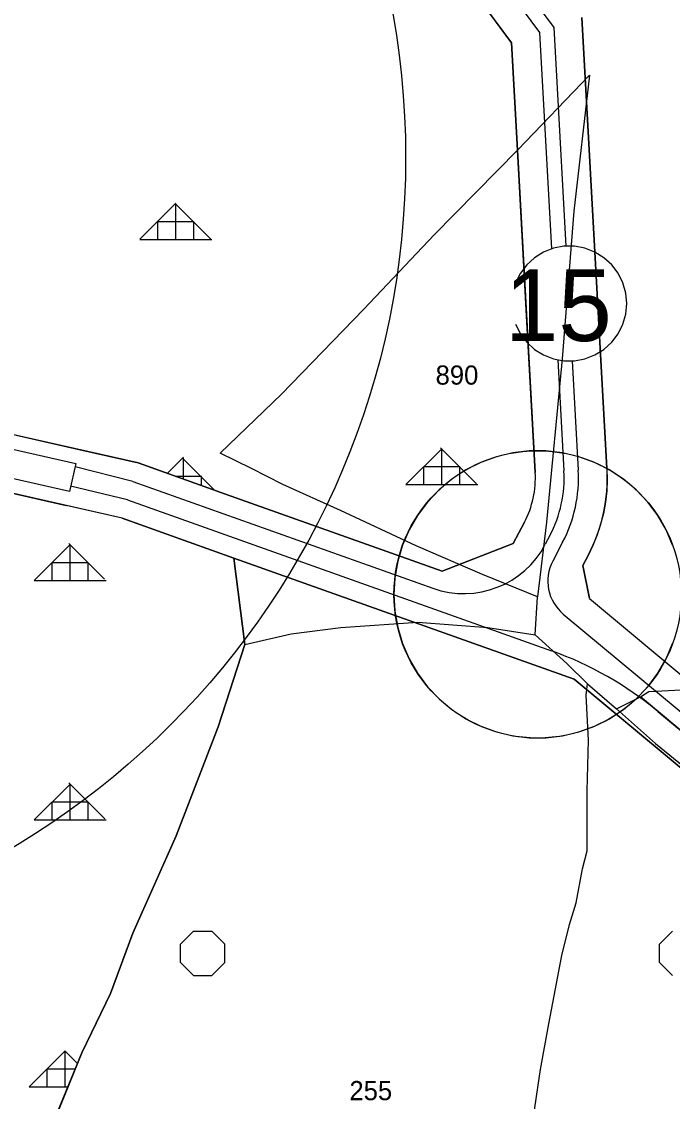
# Model space of a CAD drawing. Extents: x 410727 to 412947, y 4463506 to 4466382.
# Drawn here: x 411560.6 to 411696.5, y 4465556.3 to 4465781.8 of the extents above; entities that cross this region are included whole.
import ezdxf

# ---------------------------------------------------------------- set-up
doc = ezdxf.new("R2010")
doc.units = 0
for name, color, linetype in [('ADAKENARI', 7, 'Continuous'), ('KALDIRIM', 7, 'Continuous'), ('KAVSAK_BEYAZ', 7, 'Continuous'), ('KD_DAIRE', 7, 'Continuous'), ('KD_YGEN', 7, 'Continuous'), ('KDS_PARSEL_NO', 7, 'Continuous'), ('KDS_PL', 7, 'Continuous'), ('LJ_ÇERÇEVE', 7, 'Continuous'), ('PL_AYA_ORMAN', 7, 'Continuous'), ('PL_KA_TARIM_DIGER', 7, 'Continuous'), ('TR_AGACALANI', 7, 'Continuous'), ('TR_ORMAN', 7, 'Continuous'), ('TR_TARIMALANI', 7, 'Continuous')]:
    doc.layers.add(name, color=color, linetype=linetype)

msp = doc.modelspace()

# ---------------------------------------------------------------- linework, layer by layer
at = {"layer": 'ADAKENARI'}
for p, q in [((411615.28, 4465841.88), (411662.84, 4465777.4)), ((411682.8, 4465688.51), (411677.57, 4465782.7)), ((411662.84, 4465777.4), (411664.09, 4465754.96)), ((411664.19, 4465755.05), (411664.09, 4465754.96)), ((411664.09, 4465754.96), (411667.83, 4465687.68)), ((411584.92, 4465689.65), (411487.47, 4465711.77)), ((411451.42, 4465707.64), (411569.91, 4465680.75)), ((411581.57, 4465678.11), (411469.07, 4465703.64)), ((411581.57, 4465678.11), (411469.07, 4465703.64)), ((411572.56, 4465692.45), (411537.97, 4465700.31)), ((411603.17, 4465683.15), (411584.92, 4465689.65)), ((411648.41, 4465667.03), (411603.17, 4465683.15)), ((411581.57, 4465678.11), (411604.87, 4465669.8)), ((411581.57, 4465678.11), (411604.87, 4465669.8)), ((411665.57, 4465677.27), (411663.23, 4465672.82)), ((411663.23, 4465672.82), (411648.41, 4465667.03)), ((411677.76, 4465668.23), (411678.85, 4465670.3)), ((411604.87, 4465669.8), (411675.96, 4465644.48)), ((411604.87, 4465669.8), (411607.17, 4465651.76)), ((411679.13, 4465661.35), (411677.76, 4465668.23)), ((411679.13, 4465661.35), (411700.95, 4465643.19)), ((411607.17, 4465651.76), (411601.65, 4465634.53)), ((411675.96, 4465644.48), (411739.57, 4465591.54)), ((411601.65, 4465634.53), (411592.83, 4465611.76)), ((411592.83, 4465611.76), (411583.79, 4465591.43)), ((411583.79, 4465591.43), (411579.16, 4465578.83)), ((411579.16, 4465578.83), (411573.2, 4465566.46)), ((411573.2, 4465566.46), (411563.28, 4465542.37))]:
    msp.add_line(p, q, dxfattribs=at)
for radius in [35, 35, 20, 20]:
    msp.add_arc((411647.86, 4465686.57), radius, 332.3005, 3.1798, dxfattribs=at)
at = {"layer": 'KALDIRIM'}
for p, q in [((411622.53, 4465847.22), (411671.68, 4465780.58)), ((411620.11, 4465845.44), (411668.73, 4465779.52)), ((411668.73, 4465779.52), (411671.24, 4465734.36)), ((411671.68, 4465780.58), (411674.22, 4465734.92)), ((411672.53, 4465711.18), (411673.82, 4465688.01)), ((411675.55, 4465710.95), (411676.81, 4465688.17)), ((411583.8, 4465685.8), (411571.74, 4465688.85)), ((411582.69, 4465681.95), (411570.82, 4465684.83)), ((411583.8, 4465685.8), (411646.44, 4465663.49)), ((411582.69, 4465681.95), (411671.24, 4465650.4)), ((411670.88, 4465674.48), (411669.92, 4465672.66)), ((411673.53, 4465673.09), (411671.47, 4465669.16)), ((411673.68, 4465658.08), (411745.02, 4465598.7)), ((411693.39, 4465637.78), (411743.2, 4465596.32))]:
    msp.add_line(p, q, dxfattribs=at)
msp.add_lwpolyline([(411453.41, 4465716.42), (411571.9, 4465689.53), (411570.57, 4465683.68), (411452.08, 4465710.57)], dxfattribs=at)
for centre, radius, start, end in [((411647.86, 4465686.57), 26, 332.3005, 3.1798), ((411647.86, 4465686.57), 26, 332.3005, 3.1798), ((411647.86, 4465686.57), 29, 332.3005, 3.1798), ((411647.86, 4465686.57), 29, 332.3005, 3.1798), ((411652.9, 4465681.6), 19.23, 250.3903, 332.3005), ((411652.9, 4465681.6), 19.23, 250.3903, 332.3005), ((411679.43, 4465664.99), 8.98, 152.3005, 230.2295), ((411679.43, 4465664.99), 8.98, 152.3005, 230.2295), ((411646.8, 4465581.8), 72.83, 50.2294, 70.3903), ((411646.8, 4465581.8), 72.83, 50.2294, 70.3903)]:
    msp.add_arc(centre, radius, start, end, dxfattribs=at)
at = {"layer": 'KAVSAK_BEYAZ'}
msp.add_lwpolyline([(411696.51, 4465672.47), (411695.13, 4465675.67), (411693.38, 4465678.69), (411691.3, 4465681.49), (411688.9, 4465684.03), (411686.23, 4465686.27), (411683.32, 4465688.19), (411680.2, 4465689.75), (411676.92, 4465690.95), (411673.53, 4465691.75), (411670.06, 4465692.16), (411666.57, 4465692.16), (411663.11, 4465691.75), (411659.71, 4465690.95), (411656.43, 4465689.75), (411653.32, 4465688.19), (411650.4, 4465686.27), (411647.73, 4465684.03), (411645.34, 4465681.49), (411643.25, 4465678.69), (411641.51, 4465675.67), (411640.13, 4465672.47), (411639.13, 4465669.13), (411638.52, 4465665.69), (411638.32, 4465662.21), (411638.52, 4465658.73), (411639.13, 4465655.29), (411640.13, 4465651.95), (411641.51, 4465648.74), (411643.25, 4465645.72), (411645.34, 4465642.92), (411647.73, 4465640.39), (411650.4, 4465638.14), (411653.32, 4465636.23), (411656.43, 4465634.66), (411659.71, 4465633.47), (411663.11, 4465632.66), (411666.57, 4465632.26), (411670.06, 4465632.26), (411673.53, 4465632.66), (411676.92, 4465633.47), (411680.2, 4465634.66), (411683.32, 4465636.23), (411686.23, 4465638.14), (411688.9, 4465640.39), (411691.3, 4465642.92), (411693.38, 4465645.72), (411695.13, 4465648.74), (411696.51, 4465651.95)], dxfattribs=at)
at = {"layer": 'KD_DAIRE'}
for p, q in [((411669.56, 4465733.68), (411667.68, 4465732.51)), ((411671.63, 4465734.48), (411669.56, 4465733.68)), ((411673.8, 4465734.89), (411671.63, 4465734.48)), ((411676.02, 4465734.89), (411673.8, 4465734.89)), ((411678.19, 4465734.48), (411676.02, 4465734.89)), ((411680.26, 4465733.68), (411678.19, 4465734.48)), ((411682.14, 4465732.51), (411680.26, 4465733.68)), ((411667.68, 4465732.51), (411666.04, 4465731.02)), ((411683.78, 4465731.02), (411682.14, 4465732.51)), ((411664.71, 4465729.26), (411663.72, 4465727.27)), ((411666.04, 4465731.02), (411664.71, 4465729.26)), ((411685.11, 4465729.26), (411683.78, 4465731.02)), ((411686.1, 4465727.27), (411685.11, 4465729.26)), ((411686.71, 4465725.14), (411686.1, 4465727.27)), ((411686.91, 4465722.94), (411686.71, 4465725.14)), ((411686.71, 4465720.73), (411686.91, 4465722.94)), ((411686.91, 4465722.94), (411686.91, 4465722.94)), ((411686.1, 4465718.6), (411686.71, 4465720.73)), ((411663.72, 4465718.6), (411664.71, 4465716.62)), ((411685.11, 4465716.62), (411686.1, 4465718.6)), ((411664.71, 4465716.62), (411666.04, 4465714.85)), ((411683.78, 4465714.85), (411685.11, 4465716.62)), ((411666.04, 4465714.85), (411667.68, 4465713.36)), ((411667.68, 4465713.36), (411669.56, 4465712.2)), ((411680.26, 4465712.2), (411682.14, 4465713.36)), ((411682.14, 4465713.36), (411683.78, 4465714.85)), ((411669.56, 4465712.2), (411671.63, 4465711.4)), ((411671.63, 4465711.4), (411673.8, 4465710.99)), ((411673.8, 4465710.99), (411676.02, 4465710.99)), ((411676.02, 4465710.99), (411678.19, 4465711.4)), ((411678.19, 4465711.4), (411680.26, 4465712.2))]:
    msp.add_line(p, q, dxfattribs=at)
msp.add_circle((411668.32, 4465662.21), 30, dxfattribs=at)
at = {"layer": 'KDS_PL'}
for p, q in [((411664.19, 4465755.05), (411679.17, 4465770.61)), ((411679.17, 4465770.61), (411675.9, 4465742.23)), ((411646.75, 4465737.31), (411664.19, 4465755.05)), ((411675.9, 4465742.23), (411673.45, 4465711.38)), ((411632.04, 4465721.76), (411646.75, 4465737.31)), ((411614.88, 4465704.02), (411632.04, 4465721.76)), ((411673.45, 4465711.38), (411670.18, 4465677.27)), ((411602.08, 4465691.73), (411614.88, 4465704.02)), ((411608.62, 4465688.46), (411602.08, 4465691.73)), ((411615.16, 4465685.18), (411608.62, 4465688.46)), ((411627.14, 4465679.72), (411615.16, 4465685.18)), ((411642.94, 4465672.36), (411627.14, 4465679.72)), ((411670.18, 4465677.27), (411668.27, 4465661.71)), ((411656.83, 4465666.35), (411642.94, 4465672.36)), ((411668.27, 4465661.71), (411656.83, 4465666.35)), ((411667.82, 4465653.75), (411668.27, 4465661.71)), ((411616.87, 4465653.97), (411627.24, 4465655.3)), ((411627.24, 4465655.3), (411643.34, 4465656.4)), ((411643.34, 4465656.4), (411657.9, 4465655.3)), ((411657.9, 4465655.3), (411667.82, 4465653.75)), ((411607.17, 4465651.76), (411616.87, 4465653.97)), ((411667.82, 4465653.75), (411674.44, 4465647.79)), ((411601.65, 4465634.53), (411607.17, 4465651.76)), ((411674.44, 4465647.79), (411678.73, 4465643.55)), ((411678.42, 4465641.18), (411678.73, 4465643.55)), ((411678.73, 4465643.55), (411684.81, 4465638.29)), ((411678.94, 4465631.79), (411678.42, 4465641.18)), ((411689.77, 4465640.8), (411691.55, 4465641.9)), ((411691.55, 4465641.9), (411698.35, 4465642.24)), ((411684.81, 4465638.29), (411689.77, 4465640.8)), ((411708.29, 4465625.33), (411689.77, 4465640.8)), ((411684.81, 4465638.29), (411692.94, 4465631.07)), ((411592.83, 4465611.76), (411601.65, 4465634.53)), ((411678.63, 4465621.17), (411678.94, 4465631.79)), ((411692.94, 4465631.07), (411705.91, 4465620.45)), ((411678.69, 4465608.62), (411678.63, 4465621.17)), ((411583.79, 4465591.43), (411592.83, 4465611.76)), ((411677.71, 4465604.91), (411678.69, 4465608.62)), ((411676.4, 4465597.82), (411677.71, 4465604.91)), ((411674.99, 4465593.24), (411676.4, 4465597.82)), ((411579.16, 4465578.83), (411583.79, 4465591.43)), ((411673.35, 4465586.8), (411674.99, 4465593.24)), ((411670.63, 4465572.51), (411673.35, 4465586.8)), ((411573.2, 4465566.46), (411579.16, 4465578.83)), ((411668.89, 4465563.02), (411670.63, 4465572.51)), ((411563.28, 4465542.37), (411573.2, 4465566.46)), ((411666.06, 4465543.82), (411668.89, 4465563.02))]:
    msp.add_line(p, q, dxfattribs=at)
at = {"layer": 'LJ_ÇERÇEVE'}
msp.add_circle((411473.17, 4465753.45), 167.6, dxfattribs=at)
at = {"layer": 'PL_AYA_ORMAN'}
for points in [[(411667.83, 4465687.68), (411665.94, 4465721.64), (411664.09, 4465754.96), (411662.84, 4465777.4), (411615.28, 4465841.88)], [(411499.2, 4465782.9), (411498.42, 4465778.65), (411497.95, 4465772.2), (411496.22, 4465754.58), (411493.08, 4465740.1), (411488.52, 4465720.11), (411487.47, 4465711.77), (411537.97, 4465700.31), (411550.26, 4465697.52), (411572.56, 4465692.45), (411584.92, 4465689.65), (411603.17, 4465683.15), (411648.41, 4465667.03), (411663.23, 4465672.82), (411665.57, 4465677.27)], [(411677.57, 4465782.7), (411682.8, 4465688.51), (411682.86, 4465686.15), (411682.75, 4465683.8), (411682.48, 4465681.45), (411682.06, 4465679.13), (411681.48, 4465676.85), (411680.75, 4465674.61), (411679.87, 4465672.42), (411678.85, 4465670.3), (411677.76, 4465668.23), (411679.13, 4465661.35), (411700.95, 4465643.19)], [(411569.91, 4465680.75), (411469.07, 4465703.64)], [(411563.28, 4465542.37), (411573.2, 4465566.46), (411579.16, 4465578.83), (411583.79, 4465591.43), (411592.83, 4465611.76), (411601.65, 4465634.53), (411607.17, 4465651.76), (411604.87, 4465669.8), (411581.57, 4465678.11), (411569.91, 4465680.75)]]:
    msp.add_lwpolyline(points, dxfattribs=at)
msp.add_arc((411647.86, 4465686.57), 20, 332.3005, 3.1798, dxfattribs=at)
at = {"layer": 'PL_KA_TARIM_DIGER'}
msp.add_lwpolyline([(411706.25, 4465619.27), (411675.96, 4465644.48), (411604.87, 4465669.8), (411607.17, 4465651.76), (411601.65, 4465634.53), (411592.83, 4465611.76), (411583.79, 4465591.43), (411579.16, 4465578.83), (411573.2, 4465566.46), (411563.28, 4465542.37)], dxfattribs=at)
at = {"layer": 'TR_AGACALANI'}
msp.add_line((411665.94, 4465721.11), (411665.94, 4465721.64), dxfattribs=at)
at = {"layer": 'TR_ORMAN'}
for p, q in [((411585.29, 4465736.4), (411592.79, 4465743.9)), ((411600.14, 4465736.31), (411592.64, 4465743.81)), ((411592.8, 4465736.29), (411592.8, 4465743.79)), ((411589.05, 4465736.29), (411589.05, 4465740.04)), ((411589.05, 4465740.04), (411596.55, 4465740.04)), ((411596.55, 4465736.29), (411596.55, 4465740.04)), ((411585.3, 4465736.29), (411600.3, 4465736.29)), ((411655.57, 4465685.32), (411648.07, 4465692.82)), ((411591.01, 4465687.48), (411594.38, 4465690.85)), ((411600.84, 4465683.98), (411594.17, 4465690.65)), ((411594.39, 4465686.28), (411594.39, 4465690.65)), ((411640.82, 4465685.13), (411648.32, 4465692.63)), ((411648.32, 4465685.15), (411648.32, 4465692.65)), ((411644.57, 4465685.15), (411644.57, 4465688.9)), ((411644.57, 4465688.9), (411652.07, 4465688.9)), ((411652.07, 4465685.15), (411652.07, 4465688.9)), ((411592.65, 4465686.9), (411598.14, 4465686.9)), ((411598.14, 4465684.94), (411598.14, 4465686.9)), ((411640.82, 4465685.15), (411655.82, 4465685.15)), ((411563.24, 4465665.09), (411570.74, 4465672.59)), ((411577.93, 4465665.35), (411570.43, 4465672.85)), ((411577.93, 4465665.35), (411570.43, 4465672.85)), ((411570.74, 4465665.13), (411570.74, 4465672.63)), ((411566.99, 4465665.13), (411566.99, 4465668.88)), ((411566.99, 4465668.88), (411574.49, 4465668.88)), ((411574.49, 4465665.13), (411574.49, 4465668.88)), ((411563.24, 4465665.13), (411578.24, 4465665.13)), ((411563.24, 4465615.1), (411570.74, 4465622.6)), ((411577.96, 4465615.33), (411570.46, 4465622.83)), ((411570.74, 4465615.13), (411570.74, 4465622.63)), ((411566.99, 4465615.13), (411566.99, 4465618.88)), ((411566.99, 4465618.88), (411574.49, 4465618.88)), ((411574.49, 4465615.13), (411574.49, 4465618.88)), ((411563.24, 4465615.13), (411578.24, 4465615.13)), ((411562.18, 4465559.37), (411569.68, 4465566.87)), ((411572.28, 4465564.23), (411569.63, 4465566.88)), ((411569.68, 4465559.36), (411569.68, 4465566.86)), ((411565.93, 4465563.11), (411571.82, 4465563.11)), ((411565.93, 4465559.36), (411565.93, 4465563.11)), ((411562.18, 4465559.36), (411570.28, 4465559.36))]:
    msp.add_line(p, q, dxfattribs=at)
at = {"layer": 'TR_TARIMALANI'}
for p, q in [((411593.74, 4465589.19), (411596.45, 4465591.9)), ((411593.74, 4465589.19), (411596.45, 4465591.9)), ((411596.46, 4465591.9), (411600.29, 4465591.9)), ((411596.46, 4465591.9), (411600.29, 4465591.9)), ((411602.99, 4465589.19), (411600.28, 4465591.9)), ((411602.99, 4465589.19), (411600.28, 4465591.9)), ((411693.74, 4465589.19), (411696.45, 4465591.9)), ((411693.74, 4465589.19), (411696.45, 4465591.9)), ((411593.75, 4465585.36), (411593.75, 4465589.19)), ((411593.75, 4465585.36), (411593.75, 4465589.19)), ((411603, 4465585.36), (411603, 4465589.19)), ((411603, 4465585.36), (411603, 4465589.19)), ((411693.75, 4465585.36), (411693.75, 4465589.19)), ((411693.75, 4465585.36), (411693.75, 4465589.19)), ((411596.45, 4465582.65), (411593.74, 4465585.36)), ((411596.45, 4465582.65), (411593.74, 4465585.36)), ((411600.28, 4465582.65), (411602.99, 4465585.36)), ((411600.28, 4465582.65), (411602.99, 4465585.36)), ((411696.45, 4465582.65), (411693.74, 4465585.36)), ((411696.45, 4465582.65), (411693.74, 4465585.36)), ((411596.46, 4465582.65), (411600.29, 4465582.65)), ((411596.46, 4465582.65), (411600.29, 4465582.65))]:
    msp.add_line(p, q, dxfattribs=at)

# ---------------------------------------------------------------- texts
at = {"layer": 'KD_YGEN'}
msp.add_text('15', height=15, dxfattribs=at).set_placement((411661.49, 4465715.11))
at = {"layer": 'KDS_PARSEL_NO'}
for s, p in [('890', (411647.02, 4465706.01)), ('255', (411629.03, 4465556.58))]:
    msp.add_text(s, height=4, dxfattribs=at).set_placement(p)

doc.saveas('drawing.dxf')
